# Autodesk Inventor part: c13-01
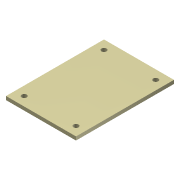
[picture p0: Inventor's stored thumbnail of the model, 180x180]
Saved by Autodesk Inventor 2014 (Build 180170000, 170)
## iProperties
Created: 2011-01
Part Number: c13-01
Material: Steel
Document SubType Name: Modeling
Designer: Thom Tremblay
Mass: 17231 g
Surface Area: 2089.64 cm^2
Volume: 2195.03 cm^3
Density: 7.85 g/cm^3
Appearance: Nylon 6
Author: Thom Tremblay
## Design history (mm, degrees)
sketch "Sketch1"
  geometry: L1 (-111.085, -169.141)-(138.915, -169.141); L2 (138.915, -169.141)-(138.915, 180.859); L3 (138.915, 180.859)-(-111.085, 180.859); L4 (-111.085, 180.859)-(-111.085, -169.141); 4 further points
  constraints: 8 end point, 2 midpoint, 2 parallel, 1 horizontal, 1 horizontal alignment, 1 perpendicular, 1 vertical alignment, 1 other
  dimensions: "d0" = 250 distance of L3.end L2.end; "d1" = 350 distance of L2.end L1.end
extrude "Extrusion1" new body sketch "Sketch1" distance "d2" = 12.7; taper "d3" = 0 deg
sketch "Sketch2"
  geometry: L1 (-111.085, -169.141)-(138.915, -169.141) reference; L2 (138.915, -169.141)-(138.915, 180.859) reference; L3 (138.915, 180.859)-(-111.085, 180.859) reference; L4 (-111.085, 180.859)-(-111.085, -169.141) reference; L5 (-78.585, 148.359)-(106.415, 148.359); L6 (106.415, 148.359)-(106.415, -136.641); L7 (106.415, -136.641)-(-78.585, -136.641); L8 (-78.585, -136.641)-(-78.585, 148.359); 1 further point
  constraints: 8 end point, 3 other
  dimensions: "d4" = 185 distance of L5.start L5.end
hole "Hole1" sketch "Sketch2" at (-78.585, 148.359), (106.415, 148.359), (106.415, -136.641), (-78.585, -136.641) diameter "d5" = 18; stored, may be unused: countersink angle "d9" = 90 deg, drill point angle "d11" = 118 deg; dims "d6" = 6, "d7" = 4, "d8" = 10.75, "d10" = 8
body "Solid1"
